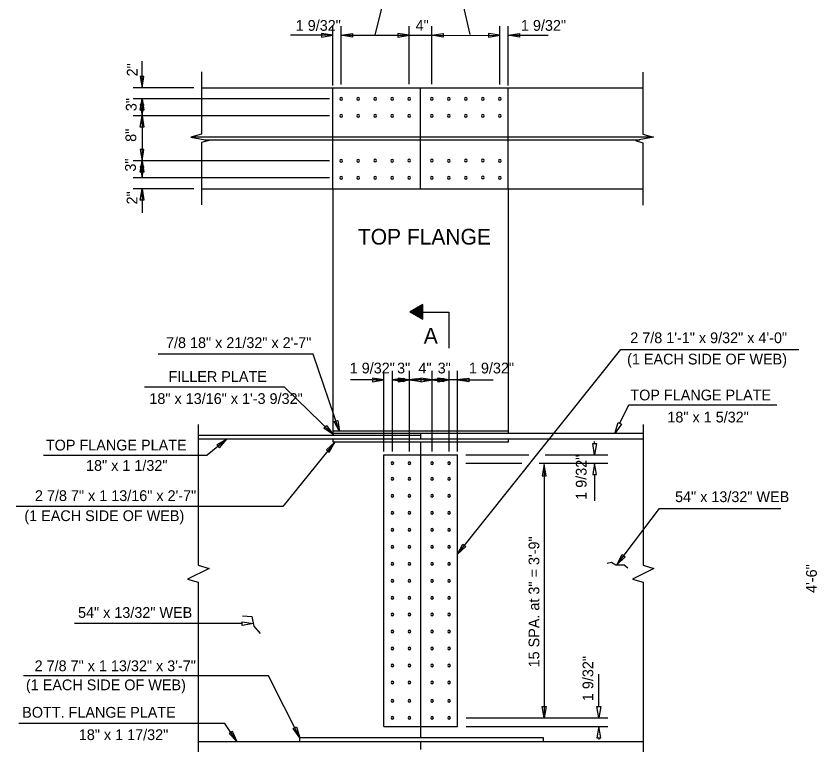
# Model space of a CAD drawing. Extents: x 4944 to 17449, y 3824 to 49087.
# Drawn here: x 11394 to 12251, y 9591 to 10371 of the extents above; entities that cross this region are included whole.
import ezdxf

# ---------------------------------------------------------------- set-up
doc = ezdxf.new("R2010")
doc.units = 0
for name, color, linetype in [('1', 7, 'Continuous'), ('2', 7, 'Continuous'), ('36_S_LINES', 7, 'Continuous'), ('3A', 7, 'Continuous'), ('4', 7, 'Continuous'), ('7', 7, 'Continuous'), ('BEAM', 7, 'Continuous'), ('Level 25', 7, 'Continuous')]:
    doc.layers.add(name, color=color, linetype=linetype)

# ---------------------------------------------------------------- blocks, each defined once
blk = doc.blocks.new('SC1136')
at = {"layer": '1'}
for p, q in [((0.4639, 0.5312), (0.5361, 0.5312)), ((0.4662, 0.5352), (0.5338, 0.5352)), ((0.4684, 0.5391), (0.5316, 0.5391)), ((0.4707, 0.543), (0.5293, 0.543)), ((0.4729, 0.5469), (0.5271, 0.5469)), ((0.4752, 0.5508), (0.5248, 0.5508)), ((0.4774, 0.5547), (0.5226, 0.5547)), ((0.4797, 0.5586), (0.5203, 0.5586)), ((0.482, 0.5625), (0.518, 0.5625)), ((0.4842, 0.5664), (0.5158, 0.5664)), ((0.4865, 0.5703), (0.5135, 0.5703)), ((0.4887, 0.5742), (0.5113, 0.5742)), ((0.491, 0.5781), (0.509, 0.5781)), ((0.4932, 0.582), (0.5068, 0.582)), ((0.4955, 0.5859), (0.5045, 0.5859)), ((0.4977, 0.5898), (0.5023, 0.5898)), ((0.4188, 0.4531), (0.5812, 0.4531)), ((0.4211, 0.457), (0.5789, 0.457)), ((0.4233, 0.4609), (0.5767, 0.4609)), ((0.4256, 0.4648), (0.5744, 0.4648)), ((0.4278, 0.4688), (0.5722, 0.4688)), ((0.4301, 0.4727), (0.5699, 0.4727)), ((0.4323, 0.4766), (0.5677, 0.4766)), ((0.4346, 0.4805), (0.5654, 0.4805)), ((0.4369, 0.4844), (0.5631, 0.4844)), ((0.4391, 0.4883), (0.5609, 0.4883)), ((0.4414, 0.4922), (0.5586, 0.4922)), ((0.4436, 0.4961), (0.5564, 0.4961)), ((0.4459, 0.5), (0.5541, 0.5)), ((0.4481, 0.5039), (0.5519, 0.5039)), ((0.4504, 0.5078), (0.5496, 0.5078)), ((0.4526, 0.5117), (0.5474, 0.5117)), ((0.4549, 0.5156), (0.5451, 0.5156)), ((0.4571, 0.5195), (0.5429, 0.5195)), ((0.4594, 0.5234), (0.5406, 0.5234)), ((0.4617, 0.5273), (0.5383, 0.5273))]:
    blk.add_line(p, q, dxfattribs=at)
blk = doc.blocks.new('DWG070')
at = {"layer": '1'}
blk.add_lwpolyline([(0, 0), (0.1406, -0.0812), (0.1406, 0.0812)], close=True, dxfattribs=at)
at = {"layer": '1', "rotation": 90}
blk.add_blockref('SC1136', (0.5945, -0.5), dxfattribs=at)
blk = doc.blocks.new('ARROWH')
at = {"layer": '1'}
blk.add_lwpolyline([(0.1231, -0.0212), (0.1231, 0.0205), (-0.0019, -0.0003)], close=True, dxfattribs=at)

msp = doc.modelspace()

# ---------------------------------------------------------------- linework, layer by layer
at = {"layer": '1'}
for centre, start, end in [((11741.94, 10282.2), 0, 180), ((11741.94, 10282.2), 180, 0), ((11760.14, 10282.26), 0, 180), ((11760.14, 10282.26), 180, 0), ((11778.33, 10282.2), 0, 180), ((11778.33, 10282.2), 180, 0), ((11796.52, 10282.26), 0, 180), ((11796.52, 10282.26), 180, 0), ((11814.71, 10282.2), 0, 180), ((11814.71, 10282.2), 180, 0), ((11838.97, 10282.2), 0, 180), ((11838.97, 10282.2), 180, 0), ((11857.16, 10282.26), 0, 180), ((11857.16, 10282.26), 180, 0), ((11875.36, 10282.2), 0, 180), ((11875.36, 10282.2), 180, 0), ((11893.55, 10282.26), 0, 180), ((11893.55, 10282.26), 180, 0), ((11911.74, 10282.2), 0, 180), ((11911.74, 10282.2), 180, 0), ((11741.94, 10263.95), 0, 180), ((11741.94, 10263.95), 180, 0), ((11760.14, 10264.01), 0, 180), ((11760.14, 10264.01), 180, 0), ((11778.33, 10263.95), 0, 180), ((11778.33, 10263.95), 180, 0), ((11796.52, 10264.01), 0, 180), ((11796.52, 10264.01), 180, 0), ((11814.71, 10263.95), 0, 180), ((11814.71, 10263.95), 180, 0), ((11838.97, 10263.95), 0, 180), ((11838.97, 10263.95), 180, 0), ((11857.16, 10264.01), 0, 180), ((11857.16, 10264.01), 180, 0), ((11875.36, 10263.95), 0, 180), ((11875.36, 10263.95), 180, 0), ((11893.55, 10264.01), 0, 180), ((11893.55, 10264.01), 180, 0), ((11911.74, 10263.95), 0, 180), ((11911.74, 10263.95), 180, 0), ((11741.94, 10215.95), 0, 180), ((11741.94, 10215.95), 180, 0), ((11760.14, 10216.01), 0, 180), ((11760.14, 10216.01), 180, 0), ((11778.33, 10216.07), 0, 180), ((11778.33, 10216.07), 180, 0), ((11796.52, 10216.01), 0, 180), ((11796.52, 10216.01), 180, 0), ((11814.71, 10216.07), 0, 180), ((11814.71, 10216.07), 180, 0), ((11838.97, 10216.07), 0, 180), ((11838.97, 10216.07), 180, 0), ((11857.16, 10216.01), 0, 180), ((11857.16, 10216.01), 180, 0), ((11875.36, 10216.07), 0, 180), ((11875.36, 10216.07), 180, 0), ((11893.55, 10216.12), 0, 180), ((11893.55, 10216.12), 180, 0), ((11911.74, 10215.95), 0, 180), ((11911.74, 10215.95), 180, 0), ((11741.94, 10197.7), 0, 180), ((11741.94, 10197.7), 180, 0), ((11760.14, 10197.76), 0, 180), ((11760.14, 10197.76), 180, 0), ((11778.33, 10197.82), 0, 180), ((11778.33, 10197.82), 180, 0), ((11796.52, 10197.76), 0, 180), ((11796.52, 10197.76), 180, 0), ((11814.71, 10197.82), 0, 180), ((11814.71, 10197.82), 180, 0), ((11838.97, 10197.82), 0, 180), ((11838.97, 10197.82), 180, 0), ((11857.16, 10197.76), 0, 180), ((11857.16, 10197.76), 180, 0), ((11875.36, 10197.82), 0, 180), ((11875.36, 10197.82), 180, 0), ((11893.55, 10197.87), 0, 180), ((11893.55, 10197.87), 180, 0), ((11911.74, 10197.7), 0, 180), ((11911.74, 10197.7), 180, 0), ((11796.7, 9892.36), 0, 180), ((11814.89, 9892.36), 0, 180), ((11839.15, 9892.36), 0, 180), ((11857.34, 9892.36), 0, 180), ((11796.7, 9892.36), 180, 0), ((11814.89, 9892.36), 180, 0), ((11839.15, 9892.36), 180, 0), ((11857.34, 9892.36), 180, 0), ((11796.7, 9875.71), 0, 180), ((11814.89, 9875.71), 0, 180), ((11839.15, 9875.71), 0, 180), ((11857.34, 9875.71), 0, 180), ((11796.7, 9875.71), 180, 0), ((11814.89, 9875.71), 180, 0), ((11839.15, 9875.71), 180, 0), ((11857.34, 9875.71), 180, 0), ((11796.7, 9857.52), 0, 180), ((11796.7, 9857.52), 180, 0), ((11814.89, 9857.52), 0, 180), ((11814.89, 9857.52), 180, 0), ((11839.15, 9857.52), 0, 180), ((11839.15, 9857.52), 180, 0), ((11857.34, 9857.52), 0, 180), ((11857.34, 9857.52), 180, 0), ((11796.7, 9839.32), 0, 180), ((11796.7, 9839.32), 180, 0), ((11814.89, 9839.32), 0, 180), ((11814.89, 9839.32), 180, 0), ((11839.15, 9839.32), 0, 180), ((11839.15, 9839.32), 180, 0), ((11857.34, 9839.32), 0, 180), ((11857.34, 9839.32), 180, 0), ((11796.7, 9821.13), 0, 180), ((11796.7, 9821.13), 180, 0), ((11814.89, 9821.13), 0, 180), ((11814.89, 9821.13), 180, 0), ((11839.15, 9821.13), 0, 180), ((11839.15, 9821.13), 180, 0), ((11857.34, 9821.13), 0, 180), ((11857.34, 9821.13), 180, 0), ((11796.7, 9802.94), 0, 180), ((11796.7, 9802.94), 180, 0), ((11814.89, 9802.94), 0, 180), ((11814.89, 9802.94), 180, 0), ((11839.15, 9802.94), 0, 180), ((11839.15, 9802.94), 180, 0), ((11857.34, 9802.94), 0, 180), ((11857.34, 9802.94), 180, 0), ((11796.7, 9784.74), 0, 180), ((11796.7, 9784.74), 180, 0), ((11814.89, 9784.74), 0, 180), ((11814.89, 9784.74), 180, 0), ((11839.15, 9784.74), 0, 180), ((11839.15, 9784.74), 180, 0), ((11857.34, 9784.74), 0, 180), ((11857.34, 9784.74), 180, 0), ((11796.7, 9766.55), 0, 180), ((11796.7, 9766.55), 180, 0), ((11814.89, 9766.55), 0, 180), ((11814.89, 9766.55), 180, 0), ((11839.15, 9766.55), 0, 180), ((11839.15, 9766.55), 180, 0), ((11857.34, 9766.55), 0, 180), ((11857.34, 9766.55), 180, 0), ((11796.7, 9748.36), 0, 180), ((11796.7, 9748.36), 180, 0), ((11814.89, 9748.36), 0, 180), ((11814.89, 9748.36), 180, 0), ((11839.15, 9748.36), 0, 180), ((11839.15, 9748.36), 180, 0), ((11857.34, 9748.36), 0, 180), ((11857.34, 9748.36), 180, 0), ((11796.7, 9730.55), 0, 180), ((11814.89, 9730.55), 0, 180), ((11839.15, 9730.55), 0, 180), ((11857.34, 9730.55), 0, 180), ((11796.7, 9730.55), 180, 0), ((11814.89, 9730.55), 180, 0), ((11839.15, 9730.55), 180, 0), ((11857.34, 9730.55), 180, 0), ((11796.7, 9712.36), 0, 180), ((11814.89, 9712.36), 0, 180), ((11839.15, 9712.36), 0, 180), ((11857.34, 9712.36), 0, 180), ((11796.7, 9712.36), 180, 0), ((11814.89, 9712.36), 180, 0), ((11839.15, 9712.36), 180, 0), ((11857.34, 9712.36), 180, 0), ((11796.7, 9694.17), 0, 180), ((11796.7, 9694.17), 180, 0), ((11814.89, 9694.17), 0, 180), ((11814.89, 9694.17), 180, 0), ((11839.15, 9694.17), 0, 180), ((11839.15, 9694.17), 180, 0), ((11857.34, 9694.17), 0, 180), ((11857.34, 9694.17), 180, 0), ((11796.7, 9675.97), 0, 180), ((11796.7, 9675.97), 180, 0), ((11814.89, 9675.97), 0, 180), ((11814.89, 9675.97), 180, 0), ((11839.15, 9675.97), 0, 180), ((11839.15, 9675.97), 180, 0), ((11857.34, 9675.97), 0, 180), ((11857.34, 9675.97), 180, 0), ((11796.7, 9657.78), 0, 180), ((11796.7, 9657.78), 180, 0), ((11814.89, 9657.78), 0, 180), ((11814.89, 9657.78), 180, 0), ((11839.15, 9657.78), 0, 180), ((11839.15, 9657.78), 180, 0), ((11857.34, 9657.78), 0, 180), ((11857.34, 9657.78), 180, 0), ((11796.7, 9638.05), 0, 180), ((11796.7, 9638.05), 180, 0), ((11814.89, 9638.05), 0, 180), ((11814.89, 9638.05), 180, 0), ((11839.15, 9638.05), 0, 180), ((11839.15, 9638.05), 180, 0), ((11857.34, 9638.05), 0, 180), ((11857.34, 9638.05), 180, 0), ((11796.7, 9619.85), 0, 180), ((11796.7, 9619.85), 180, 0), ((11814.89, 9619.85), 0, 180), ((11814.89, 9619.85), 180, 0), ((11839.15, 9619.85), 0, 180), ((11839.15, 9619.85), 180, 0), ((11857.34, 9619.85), 0, 180), ((11857.34, 9619.85), 180, 0)]:
    msp.add_arc(centre, 1.42, start, end, dxfattribs=at)
at = {"layer": '2'}
for p, q in [((11826.84, 10185.99), (11826.84, 10293.99)), ((11827.02, 9610.76), (11827.02, 9901.46))]:
    msp.add_line(p, q, dxfattribs=at)
at = {"layer": '36_S_LINES'}
for p, q in [((11732.9, 10296.64), (11732.9, 10359.81)), ((11920.78, 10296.64), (11920.78, 10359.81)), ((11732.9, 10350.19), (11687.77, 10350.19)), ((11742, 10350.19), (11814.71, 10350.21)), ((11814.71, 10350.21), (11839.09, 10350.22)), ((11839.09, 10350.22), (11911.68, 10350.14)), ((11920.78, 10350.19), (11963.4, 10350.19)), ((11528.72, 10293.99), (11528.72, 10322.36)), ((11592.31, 10310.96), (11592.31, 10244.53)), ((12064.91, 10310.84), (12064.91, 10244.42)), ((11584.04, 10293.99), (11519.1, 10293.99)), ((11528.72, 10282.2), (11528.72, 10264.01)), ((11528.72, 10282.2), (11528.72, 10264.01)), ((11528.72, 10270.07), (11528.72, 10209.95)), ((11528.72, 10270.07), (11528.72, 10203.86)), ((11592.31, 10244.53), (11580.94, 10241.35)), ((11580.94, 10241.35), (11600.34, 10237.57)), ((11600.34, 10237.57), (11592.31, 10235.32)), ((12076.28, 10241.23), (12056.88, 10237.45)), ((12056.88, 10237.45), (12064.91, 10235.21)), ((12064.91, 10244.42), (12076.28, 10241.23)), ((11592.31, 10235.32), (11592.31, 10168.67)), ((12064.91, 10235.21), (12064.91, 10168.56)), ((11528.72, 10197.82), (11528.72, 10216.01)), ((11528.72, 10197.82), (11528.72, 10216.01)), ((11584.04, 10185.99), (11519.1, 10185.99)), ((11528.72, 10185.99), (11528.72, 10160.33)), ((11866.44, 9794.96), (12041.13, 10014.07)), ((12041.13, 10014.07), (12231.89, 10014.07)), ((11711.91, 10008.91), (11545.98, 10008.91)), ((11740.21, 9926.1), (11711.91, 10008.91)), ((11787.6, 9904.71), (11787.6, 9991.1)), ((11866.44, 9904.71), (11866.44, 9991.1)), ((11787.6, 9981.47), (11751.98, 9981.47)), ((11839.15, 9981.47), (11796.7, 9981.47)), ((11796.7, 9981.47), (11814.89, 9981.47)), ((11839.15, 9981.47), (11814.89, 9981.47)), ((11814.89, 9981.47), (11814.89, 9981.47)), ((11857.34, 9981.47), (11814.89, 9981.47)), ((11857.34, 9981.47), (11833.09, 9981.47)), ((11875.54, 9981.47), (11857.34, 9981.47)), ((11866.44, 9981.47), (11904.62, 9981.47)), ((11681.11, 9973.59), (11531.45, 9973.59)), ((11733.26, 9922.98), (11681.11, 9973.59)), ((12040.17, 9935), (12049.75, 9954.68)), ((12049.75, 9954.68), (12208.12, 9954.68)), ((11588.96, 9933.61), (11588.96, 9783.19)), ((12065.09, 9933.61), (12065.09, 9783.19)), ((11619.66, 9918.11), (11598.54, 9901.1)), ((11735.16, 9914.71), (11679.62, 9846.11)), ((12013.2, 9913.58), (12013.2, 9915.52)), ((11423.17, 9901.1), (11598.54, 9901.1)), ((11875.23, 9901.46), (11942.84, 9901.46)), ((11960.12, 9901.46), (12027.23, 9901.46)), ((11959.18, 9890.82), (11959.18, 9621.4)), ((12013.2, 9880.23), (12013.2, 9852.13)), ((11679.62, 9846.11), (11393.87, 9846.11)), ((12037.03, 9783.62), (12082.5, 9844)), ((12082.5, 9844), (12212.59, 9844)), ((11588.96, 9783.19), (11600.48, 9779.78)), ((12026.73, 9785.42), (12031.34, 9786.28)), ((12031.34, 9786.28), (12035.9, 9783.5)), ((12035.9, 9783.5), (12040.41, 9783.5)), ((12040.41, 9783.5), (12044.97, 9783.45)), ((12044.97, 9783.45), (12048.81, 9780.34)), ((12065.09, 9783.19), (12076.61, 9779.78)), ((11600.48, 9779.78), (11577.43, 9768.43)), ((12076.61, 9779.78), (12053.57, 9768.43)), ((11577.43, 9768.43), (11588.96, 9765.02)), ((11588.96, 9765.02), (11588.96, 9579.39)), ((12053.57, 9768.43), (12065.09, 9765.02)), ((12065.09, 9765.02), (12065.09, 9579.39)), ((11636.3, 9729.2), (11646.31, 9728.31)), ((11646.31, 9728.31), (11648.31, 9718.09)), ((11635.91, 9720.65), (11456.53, 9720.65)), ((11648.31, 9718.09), (11655.2, 9710.09)), ((11664.12, 9664.87), (11401.71, 9664.87)), ((11697.64, 9598.61), (11664.12, 9664.87)), ((12017.67, 9631.98), (12017.67, 9666.53)), ((11617.36, 9613.73), (11396.91, 9613.73)), ((11630.57, 9594.11), (11617.36, 9613.73)), ((11875.77, 9610.76), (12027.23, 9610.76)), ((12017.67, 9598.63), (12017.67, 9596.6))]:
    msp.add_line(p, q, dxfattribs=at)
msp.add_lwpolyline([(11778.36, 10350.2), (11790.27, 10399.42), (11868.56, 10399.42), (11879.6, 10350.89)], dxfattribs=at)
for points in [[(11720.77, 10352.21), (11720.77, 10348.17), (11732.9, 10350.19)], [(11754.13, 10352.21), (11754.13, 10348.17), (11742, 10350.19)], [(11802.58, 10352.27), (11802.58, 10348.22), (11814.71, 10350.24)], [(11851.1, 10352.27), (11851.1, 10348.22), (11838.97, 10350.24)], [(11899.56, 10352.21), (11899.56, 10348.17), (11911.68, 10350.19)], [(11932.91, 10352.21), (11932.91, 10348.17), (11920.78, 10350.19)], [(11530.74, 10306.11), (11526.7, 10306.11), (11528.72, 10293.99)], [(11529.73, 10301.98), (11527.71, 10301.98), (11528.72, 10293.99)], [(11529.73, 10301.98), (11527.71, 10301.98), (11528.72, 10293.99)], [(11530.74, 10270.07), (11526.7, 10270.07), (11528.72, 10282.2)], [(11529.73, 10274.21), (11527.71, 10274.21), (11528.72, 10282.2)], [(11529.73, 10274.21), (11527.71, 10274.21), (11528.72, 10282.2)], [(11530.74, 10276.14), (11526.7, 10276.14), (11528.72, 10264.01)], [(11529.73, 10272.01), (11527.71, 10272.01), (11528.72, 10264.01)], [(11529.73, 10272.01), (11527.71, 10272.01), (11528.72, 10264.01)], [(11530.74, 10251.88), (11526.7, 10251.88), (11528.72, 10264.01)], [(11529.73, 10256.01), (11527.71, 10256.01), (11528.72, 10264.01)], [(11529.73, 10256.01), (11527.71, 10256.01), (11528.72, 10264.01)], [(11530.74, 10228.14), (11526.7, 10228.14), (11528.72, 10216.01)], [(11529.73, 10224.01), (11527.71, 10224.01), (11528.72, 10216.01)], [(11529.73, 10224.01), (11527.71, 10224.01), (11528.72, 10216.01)], [(11530.74, 10203.88), (11526.7, 10203.88), (11528.72, 10216.01)], [(11529.73, 10208.01), (11527.71, 10208.01), (11528.72, 10216.01)], [(11529.73, 10208.01), (11527.71, 10208.01), (11528.72, 10216.01)], [(11530.74, 10209.94), (11526.7, 10209.94), (11528.72, 10197.82)], [(11529.73, 10205.81), (11527.71, 10205.81), (11528.72, 10197.82)], [(11529.73, 10205.81), (11527.71, 10205.81), (11528.72, 10197.82)], [(11530.74, 10173.86), (11526.7, 10173.86), (11528.72, 10185.99)], [(11529.73, 10177.99), (11527.71, 10177.99), (11528.72, 10185.99)], [(11529.73, 10177.99), (11527.71, 10177.99), (11528.72, 10185.99)], [(11775.48, 9983.49), (11775.48, 9979.45), (11787.6, 9981.47)], [(11779.61, 9980.46), (11779.61, 9982.48), (11787.6, 9981.47)], [(11779.61, 9982.48), (11779.61, 9980.46), (11787.6, 9981.47)], [(11779.63, 9980.46), (11779.63, 9982.48), (11787.6, 9981.47)], [(11808.83, 9983.49), (11808.83, 9979.45), (11796.7, 9981.47)], [(11804.68, 9980.46), (11804.68, 9982.48), (11796.7, 9981.47)], [(11804.7, 9980.46), (11804.7, 9982.48), (11796.7, 9981.47)], [(11804.7, 9982.48), (11804.7, 9980.46), (11796.7, 9981.47)], [(11802.77, 9983.49), (11802.77, 9979.45), (11814.89, 9981.47)], [(11806.9, 9980.46), (11806.9, 9982.48), (11814.89, 9981.47)], [(11806.9, 9982.48), (11806.9, 9980.46), (11814.89, 9981.47)], [(11806.91, 9980.46), (11806.91, 9982.48), (11814.89, 9981.47)], [(11827.02, 9983.49), (11827.02, 9979.45), (11814.89, 9981.47)], [(11822.87, 9980.46), (11822.87, 9982.48), (11814.89, 9981.47)], [(11822.89, 9980.46), (11822.89, 9982.48), (11814.89, 9981.47)], [(11822.89, 9982.48), (11822.89, 9980.46), (11814.89, 9981.47)], [(11827.02, 9983.49), (11827.02, 9979.45), (11839.15, 9981.47)], [(11831.15, 9980.46), (11831.15, 9982.48), (11839.15, 9981.47)], [(11831.15, 9982.48), (11831.15, 9980.46), (11839.15, 9981.47)], [(11831.17, 9980.46), (11831.17, 9982.48), (11839.15, 9981.47)], [(11851.28, 9983.49), (11851.28, 9979.45), (11839.15, 9981.47)], [(11847.13, 9980.46), (11847.13, 9982.48), (11839.15, 9981.47)], [(11847.15, 9980.46), (11847.15, 9982.48), (11839.15, 9981.47)], [(11847.15, 9982.48), (11847.15, 9980.46), (11839.15, 9981.47)], [(11845.21, 9983.49), (11845.21, 9979.45), (11857.34, 9981.47)], [(11849.35, 9980.46), (11849.35, 9982.48), (11857.34, 9981.47)], [(11849.35, 9982.48), (11849.35, 9980.46), (11857.34, 9981.47)], [(11849.36, 9980.46), (11849.36, 9982.48), (11857.34, 9981.47)], [(11878.57, 9983.49), (11878.57, 9979.45), (11866.44, 9981.47)], [(11874.42, 9980.46), (11874.42, 9982.48), (11866.44, 9981.47)], [(11738.22, 9938.1), (11740.21, 9926.1), (11734.44, 9936.8)], [(11726.05, 9932.77), (11733.26, 9922.98), (11723.26, 9929.9)], [(12038.36, 9935.89), (12041.99, 9934.12), (12034.87, 9924.1)], [(11608.98, 9912.1), (11611.51, 9908.95), (11619.69, 9918.14)], [(11729.17, 9904.12), (11735.16, 9914.71), (11726.06, 9906.64)], [(12011.18, 9913.58), (12015.22, 9913.58), (12013.2, 9901.46)], [(11957.16, 9878.69), (11961.2, 9878.69), (11959.18, 9890.82)], [(12011.18, 9880.23), (12015.22, 9880.23), (12013.2, 9892.36)], [(11872.19, 9805.83), (11875.41, 9803.38), (11866.44, 9794.96)], [(12042.78, 9794.49), (12046, 9792.03), (12037.03, 9783.62)], [(11635.91, 9718.63), (11635.91, 9722.67), (11648.04, 9720.65)], [(11957.16, 9631.98), (11961.2, 9631.98), (11959.18, 9619.85)], [(12015.65, 9631.98), (12019.69, 9631.98), (12017.67, 9619.85)], [(12015.65, 9598.63), (12019.69, 9598.63), (12017.67, 9610.76)], [(11694.01, 9610.22), (11697.64, 9598.61), (11690.44, 9608.41)]]:
    msp.add_lwpolyline(points, close=True, dxfattribs=at)
at = {"layer": '3A'}
for p, q in [((11742, 10297.72), (11742, 10359.81)), ((11814.71, 10297.77), (11814.71, 10359.87)), ((11838.97, 10297.77), (11838.97, 10359.87)), ((11911.68, 10297.72), (11911.68, 10359.81)), ((11729.58, 10282.14), (11519.1, 10282.2)), ((11729.36, 10263.95), (11519.1, 10264.01)), ((11729.36, 10215.95), (11519.1, 10216.01)), ((11729.58, 10197.76), (11519.1, 10197.82)), ((11796.7, 9904.71), (11796.7, 9991.1)), ((11814.89, 9904.71), (11814.89, 9991.1)), ((11839.15, 9904.71), (11839.15, 9991.1)), ((11857.34, 9904.71), (11857.34, 9991.1)), ((11875.23, 9892.36), (11935.28, 9892.36)), ((11953.85, 9892.36), (12027.23, 9892.36)), ((11875.77, 9619.85), (12027.23, 9619.85))]:
    msp.add_line(p, q, dxfattribs=at)
at = {"layer": '4'}
for p, q in [((11815.74, 10054.07), (11857.17, 10054.07)), ((11857.17, 10054.07), (11857.17, 10015.48))]:
    msp.add_line(p, q, dxfattribs=at)
at = {"layer": '7'}
for p, q in [((11581.48, 10241.5), (12075.73, 10241.39)), ((11595.7, 10238.47), (12061.51, 10238.36))]:
    msp.add_line(p, q, dxfattribs=at)
at = {"layer": 'DEFPOINTS'}
for p, q in [((11732.9, 10185.99), (11732.9, 9926.73)), ((11920.78, 10185.87), (11920.78, 9926.73)), ((11627.73, 9664.87), (11627.73, 9664.87))]:
    msp.add_line(p, q, dxfattribs=at)
at = {"layer": 'Level 25'}
for p, q in [((11592.31, 10293.99), (12064.91, 10293.87)), ((11732.9, 10185.93), (11732.9, 10293.93)), ((11920.78, 10185.93), (11920.78, 10293.93)), ((11592.31, 10185.99), (12064.91, 10185.87)), ((11827.02, 9921.86), (11588.96, 9921.86)), ((11733.26, 9924.11), (11733.26, 9926.73)), ((11921.14, 9926.73), (11733.26, 9926.73)), ((12065.09, 9924.11), (11733.26, 9924.11)), ((11733.26, 9924.11), (11733.26, 9921.86)), ((11827.02, 9918.11), (11827.02, 9924.11)), ((11921.14, 9924.11), (11921.14, 9926.73)), ((12065.09, 9918.11), (11588.96, 9918.11)), ((11733.26, 9914.71), (11733.26, 9918.11)), ((11921.14, 9914.71), (11733.26, 9914.71)), ((11827.02, 9901.46), (11827.02, 9914.71)), ((11921.14, 9914.71), (11921.14, 9918.11)), ((11787.6, 9901.46), (11866.44, 9901.46)), ((11787.6, 9610.76), (11787.6, 9901.46)), ((11866.44, 9610.76), (11866.44, 9901.46)), ((11787.6, 9610.76), (11866.44, 9610.76)), ((11827.02, 9599.67), (11827.02, 9610.76)), ((12065.09, 9594.11), (11588.96, 9594.11)), ((11958.31, 9598.61), (11697.67, 9598.61)), ((11697.67, 9594.11), (11697.67, 9598.55)), ((11827.02, 9586.14), (11827.02, 9594.11)), ((11958.31, 9594.11), (11958.31, 9598.55))]:
    msp.add_line(p, q, dxfattribs=at)

# ---------------------------------------------------------------- block references
at = {"layer": '36_S_LINES', "xscale": 97.0280040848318, "yscale": 97.02800408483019, "rotation": 123.60584756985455}
msp.add_blockref('ARROWH', (11630.44, 9594.24), dxfattribs=at)
at = {"layer": '4', "xscale": 97.02800408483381, "yscale": 97.02800408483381}
msp.add_blockref('DWG070', (11815.74, 10054.29), dxfattribs=at)

# ---------------------------------------------------------------- texts
at = {"layer": '3A'}
for s, p in [('1 9/32"', (11693.24, 10354.99)), ('4"', (11821.61, 10355.05)), ('1 9/32"', (11934.3, 10354.99)), ('2 7/8 1\'-1" x 9/32" x 4\'-0"', (12051.31, 10020.78)), ('7/8 18" x 21/32" x 2\'-7"', (11554.42, 10015.54)), ('(1 EACH SIDE OF WEB)', (12047.95, 9998)), ('1 9/32"', (11751.05, 9988.4)), ('3"', (11801.76, 9988.4)), ('4"', (11824.6, 9988.4)), ('3"', (11845.17, 9988.4)), ('1 9/32"', (11878.64, 9988.4)), ('FILLER PLATE', (11557.1, 9979.3)), ('TOP FLANGE PLATE', (12051.43, 9959.54)), ('18" x 13/16" x 1\'-3 9/32"', (11536.61, 9955.7)), ('18" x 1 5/32"', (12091.06, 9935.93)), ('TOP FLANGE PLATE', (11425.84, 9905.96)), ('18" x 1 1/32"', (11468.85, 9884.15)), ('2 7/8 7" x 1 13/16" x 2\'-7"', (11414.1, 9851.85)), ('54" x 13/32" WEB', (12099.28, 9850.71)), ('(1 EACH SIDE OF WEB)', (11402.8, 9830.39)), ('54" x 13/32" WEB', (11460.25, 9726.8)), ('2 7/8 7" x 1 13/32" x 3\'-7"', (11413.73, 9669.8)), ('(1 EACH SIDE OF WEB)', (11404.48, 9649.41)), ('BOTT. FLANGE PLATE', (11400.5, 9620.04)), ('18" x 1 17/32"', (11461.09, 9596.07))]:
    msp.add_text(s, height=11.52, dxfattribs=at).set_placement(p)
for s, p in [('2"', (11524.02, 10306.22)), ('3"', (11522.94, 10269.01)), ('8"', (11522.55, 10236.2)), ('3"', (11522.16, 10204.31)), ('2"', (11523.8, 10169.16)), ('1 9/32"', (12004.6, 9853.17)), ('15 SPA. at 3" = 3\'-9"', (11954.02, 9673.82)), ('1 9/32"', (12011.81, 9637.72))]:
    msp.add_text(s, height=11.52, rotation=90, dxfattribs=at).set_placement(p)
at = {"layer": 'BEAM'}
for s, height, p in [('TOP FLANGE', 16.8, (11759.83, 10126.28)), ('A', 16.98, (11830.23, 10020.15))]:
    msp.add_text(s, height=height, dxfattribs=at).set_placement(p)
at = {"layer": 'DEFPOINTS'}
msp.add_text('4\'-6"', height=11.52, rotation=90, dxfattribs=at).set_placement((12251.04, 9753.52))

doc.saveas('drawing.dxf')
